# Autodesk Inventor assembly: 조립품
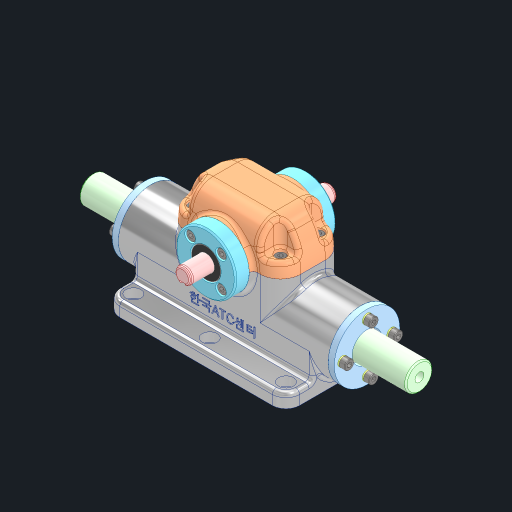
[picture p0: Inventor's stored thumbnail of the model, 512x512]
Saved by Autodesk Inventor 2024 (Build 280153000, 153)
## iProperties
Created: 2024-06
Part Number: 조립품
Document SubType Name: Assembly
Designer: kh_501
Author: kh_501
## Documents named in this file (16)
- C:\Users\kh_501\Desktop\740604V1005\조립품.iam
- C:\Users\kh_501\Desktop\740604V1005\본체.ipt
- C:\Users\kh_501\Desktop\740604V1005\깊은 홈 볼 베어링 6901\깊은 홈 볼 베어링 6901.ipt
- C:\Users\kh_501\Desktop\740604V1005\랙\랙.ipt
- C:\Users\kh_501\Desktop\740604V1005\베어링 커버\베어링 커버.ipt
- C:\Users\kh_501\Desktop\740604V1005\부시 커버\부시 커버.ipt
- C:\Users\kh_501\Desktop\740604V1005\스프링 와셔 M4\스프링 와셔 M4.ipt
- C:\Users\kh_501\Desktop\740604V1005\오일레스 부시\오일레스 부시.ipt
- C:\Users\kh_501\Desktop\740604V1005\오일실 12 22 7\오일실 12 22 7.ipt
- C:\Users\kh_501\Desktop\740604V1005\윗커버\윗커버.ipt
- C:\Users\kh_501\Desktop\740604V1005\육각 소켓 머리 볼트 M4x10\육각 소켓 머리 볼트 M4x10.ipt
- C:\Users\kh_501\Desktop\740604V1005\칼라\칼라.ipt
- C:\Users\kh_501\Desktop\740604V1005\피니언\피니언.ipt
- C:\Users\kh_501\Desktop\740604V1005\육각 소켓 머리 볼트 M4x10\육각 소켓 머리 볼트 M4x10_MIR.ipt
- C:\Users\kh_501\Desktop\740604V1005\육각 소켓 머리 볼트 M4x10\육각 소켓 머리 볼트 M4x10_MIR_MIR.ipt
- C:\Users\kh_501\Desktop\740604V1005\육각 소켓 머리 볼트 M4x10\육각 소켓 머리 볼트 M4x10_MIR_MIR_MIR.ipt
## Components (1 placed, 1 different names)
1. 피니언:1
